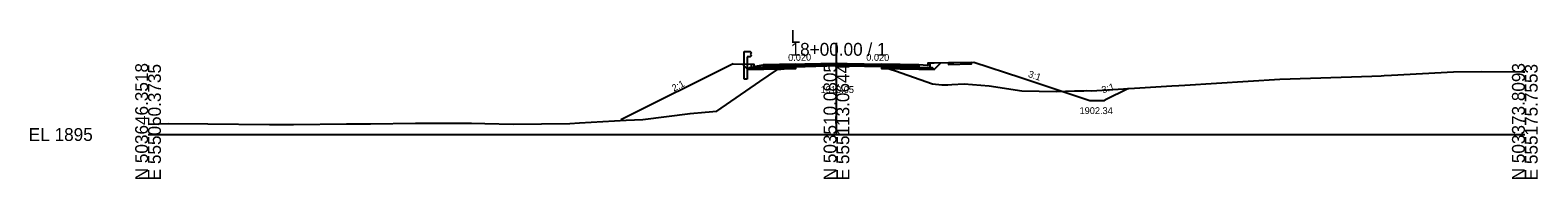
# Model space of a CAD drawing. Extents: x -26 to 4603, y -10 to 4703.
# Drawn here: x -25.7 to 302.8, y 3535.3 to 3567.8 of the extents above; entities that cross this region are included whole.
import ezdxf

# ---------------------------------------------------------------- set-up
doc = ezdxf.new("R2010")
doc.units = 0
for name, color, linetype in [('Default', 7, 'Continuous'), ('Exist Cross Section Cell', 7, 'Continuous'), ('Exist XS Ground Line', 7, 'Continuous'), ('Prop CMT Guardrail Graphics', 7, 'Continuous'), ('Prop CMT Pvmt Course 1', 7, 'Continuous'), ('Prop CMT Pvmt Course 2', 7, 'Continuous'), ('Prop CMT Pvmt Course 3', 7, 'Continuous'), ('Prop CMT Pvmt Milling', 7, 'Continuous'), ('Prop CMT Shear Line', 7, 'Continuous'), ('Prop CMT Shld Paved Course 2', 7, 'Continuous'), ('Prop CMT Shld Paved Course 3', 7, 'Continuous'), ('Prop CMT Subgrade Earthwork', 7, 'Continuous'), ('Prop Conc 4in Sidewalk', 7, 'Continuous'), ('Prop Conc Curb and Gutter', 7, 'Continuous'), ('Prop XS Ditch Slope Text', 7, 'Continuous'), ('Prop XS Finish Grade', 7, 'Continuous'), ('Prop XS Label Text', 7, 'Continuous'), ('Prop XS SS Elevation Text', 7, 'Continuous'), ('Scratch_Level_9', 7, 'Continuous')]:
    doc.layers.add(name, color=color, linetype=linetype)

msp = doc.modelspace()

# ---------------------------------------------------------------- linework, layer by layer
at = {"layer": 'Exist Cross Section Cell'}
for p, q in [((150, 3545), (150, 3565)), ((0, 3545), (150, 3545)), ((150, 3545), (300, 3545))]:
    msp.add_line(p, q, dxfattribs=at)
at = {"layer": 'Exist XS Ground Line'}
msp.add_lwpolyline([(0, 3547.27), (4.47, 3547.38), (13.05, 3547.35), (26.48, 3547.18), (28.13, 3547.18), (31.7, 3547.17), (43.21, 3547.34), (48.5, 3547.34), (58.28, 3547.49), (70.51, 3547.47), (73.36, 3547.44), (79.56, 3547.29), (91.93, 3547.41), (93.99, 3547.55), (104.17, 3548.15), (107.83, 3548.28), (118.15, 3549.59), (121.37, 3549.89), (123.97, 3550.12), (133.34, 3556.58), (137.13, 3559.17), (138.59, 3559.37), (141.18, 3559.78), (143.22, 3559.84), (150.24, 3560.06), (152.35, 3560.02), (159.79, 3559.86), (162.84, 3558.87), (170.92, 3556.08), (173, 3555.88), (174.28, 3555.83), (175.14, 3555.91), (177.8, 3556.06), (183.3, 3555.62), (190.37, 3554.57), (197.94, 3554.39), (201.84, 3554.51), (203.9, 3554.57), (204.55, 3554.6), (205.6, 3554.54), (223.12, 3555.63), (224.62, 3555.71), (225.89, 3555.78), (246.63, 3557.06), (266.66, 3557.73), (268.68, 3557.81), (269.38, 3557.85), (270.97, 3557.94), (284.46, 3558.69), (290.66, 3558.74), (299.54, 3558.67), (300, 3558.7)], dxfattribs=at)
at = {"layer": 'Prop CMT Guardrail Graphics'}
for points in [[(129.89, 3557.12), (129.89, 3563.12)], [(129.89, 3563.12), (131.23, 3563.12), (131.5, 3562.83)], [(131.5, 3562.25), (131.23, 3561.95), (130.56, 3561.95)], [(130.56, 3561.95), (130.56, 3557.12)], [(131.5, 3562.83), (131.23, 3562.54)], [(131.23, 3562.54), (131.5, 3562.25)], [(130.56, 3557.12), (129.89, 3557.12)]]:
    msp.add_lwpolyline(points, dxfattribs=at)
at = {"layer": 'Prop CMT Pvmt Course 1'}
for points in [[(141.18, 3560.38), (134, 3560.24), (134, 3559.99), (134, 3559.99), (141.18, 3560.13), (141.18, 3560.13), (141.18, 3560.13), (141.18, 3560.38), (141.18, 3560.38)], [(150, 3560.56), (150, 3560.56), (150, 3560.05), (150, 3560.05), (150, 3560.05), (143.22, 3559.84), (143.22, 3559.84), (141.18, 3559.78), (141.18, 3559.78), (141.18, 3560.38), (143.22, 3560.43), (143.22, 3560.43), (150, 3560.56)], [(159.79, 3560.36), (159.79, 3559.86), (159.79, 3559.86), (159.79, 3559.86), (152.35, 3560.02), (152.35, 3560.02), (150.24, 3560.06), (150, 3560.05), (150, 3560.05), (150, 3560.05), (150, 3560.56), (150.24, 3560.56), (150.24, 3560.56), (152.35, 3560.51), (152.35, 3560.51), (159.79, 3560.36), (159.79, 3560.36)], [(167.95, 3560.2), (159.79, 3560.36), (159.79, 3560.11), (159.79, 3560.11), (167.95, 3559.95), (167.95, 3559.95), (167.95, 3559.95), (167.95, 3560.2), (167.95, 3560.2)]]:
    msp.add_lwpolyline(points, dxfattribs=at)
at = {"layer": 'Prop CMT Pvmt Course 2'}
for points in [[(141.18, 3560.13), (134, 3559.99), (134, 3559.66), (134, 3559.66), (141.18, 3559.8), (141.18, 3559.8), (141.18, 3559.8), (141.18, 3560.13), (141.18, 3560.13)], [(167.95, 3559.95), (159.79, 3560.11), (159.79, 3559.78), (159.79, 3559.78), (167.95, 3559.62), (167.95, 3559.62), (167.95, 3559.62), (167.95, 3559.95), (167.95, 3559.95)]]:
    msp.add_lwpolyline(points, dxfattribs=at)
at = {"layer": 'Prop CMT Pvmt Course 3'}
for points in [[(141.18, 3559.8), (134, 3559.66), (134, 3559.28), (134, 3559.28), (141.18, 3559.43), (141.18, 3559.43), (141.18, 3559.43), (141.18, 3559.8), (141.18, 3559.8)], [(167.95, 3559.62), (159.79, 3559.78), (159.79, 3559.41), (159.79, 3559.41), (167.95, 3559.24), (167.95, 3559.24), (167.95, 3559.24), (167.95, 3559.62), (167.95, 3559.62)], [(167.95, 3559.62), (167.95, 3559.24), (167.95, 3559.24), (171.33, 3559.17), (170.95, 3559.55), (167.95, 3559.62), (167.95, 3559.62)]]:
    msp.add_lwpolyline(points, dxfattribs=at)
at = {"layer": 'Prop CMT Pvmt Milling'}
for points in [[(141.18, 3559.78), (143.22, 3559.84), (143.22, 3559.84), (150, 3560.05), (150, 3560.05)], [(152.35, 3560.02), (159.79, 3559.86), (159.79, 3559.86), (159.79, 3559.86), (159.79, 3559.86), (152.35, 3560.02), (152.35, 3560.02), (150.24, 3560.06), (150, 3560.05), (150, 3560.05)]]:
    msp.add_lwpolyline(points, dxfattribs=at)
at = {"layer": 'Prop CMT Shld Paved Course 2'}
for points in [[(150, 3560.31), (150, 3560.31), (150, 3559.98), (150, 3559.98), (150, 3559.98), (143.22, 3559.84), (143.22, 3559.84), (143.05, 3559.84), (141.18, 3559.78), (141.18, 3559.78), (141.18, 3559.78), (141.18, 3560.13), (143.22, 3560.18), (143.22, 3560.18), (150, 3560.31)], [(159.79, 3560.11), (159.79, 3559.78), (159.79, 3559.78), (159.79, 3559.78), (152.35, 3559.93), (152.35, 3559.93), (150.24, 3559.97), (150.24, 3559.97), (150, 3559.98), (150, 3559.98), (150, 3560.31), (150.24, 3560.31), (150.24, 3560.31), (152.35, 3560.26), (152.35, 3560.26), (159.79, 3560.11), (159.79, 3560.11)]]:
    msp.add_lwpolyline(points, dxfattribs=at)
at = {"layer": 'Prop CMT Shld Paved Course 3'}
msp.add_lwpolyline([(131, 3559.6), (134, 3559.66), (134, 3559.28), (134, 3559.28), (130.7, 3559.22), (130.7, 3559.22), (130.7, 3559.22), (131, 3559.6), (131, 3559.6)], dxfattribs=at)
at = {"layer": 'Prop CMT Subgrade Earthwork'}
for points in [[(129.54, 3560.38), (130.7, 3559.22), (130.7, 3559.22)], [(130.7, 3559.22), (141.18, 3559.43), (141.18, 3559.43)], [(171.33, 3559.18), (171.33, 3559.18), (159.79, 3559.41)], [(167.95, 3559.24), (167.95, 3559.24), (171.33, 3559.17), (172.78, 3560.62)]]:
    msp.add_lwpolyline(points, dxfattribs=at)
at = {"layer": 'Prop Conc 4in Sidewalk'}
msp.add_lwpolyline([(174.45, 3560.65), (174.45, 3560.32), (179.45, 3560.42), (179.45, 3560.75), (174.45, 3560.65)], dxfattribs=at)
at = {"layer": 'Prop Conc Curb and Gutter'}
for points in [[(132, 3559.84), (134, 3560.24), (134, 3559.66), (134, 3559.66), (131.5, 3559.61), (131.5, 3559.61), (131.5, 3559.61), (131.5, 3560.34), (132, 3560.34), (132, 3560.34), (132, 3559.84), (132, 3559.84), (132, 3559.84)], [(167.95, 3560.2), (167.95, 3560.2), (167.95, 3560.2), (167.95, 3559.62), (167.95, 3559.62), (167.95, 3559.62), (170.29, 3559.57), (170.45, 3559.56), (170.45, 3559.63), (170.45, 3560.58), (169.97, 3560.58), (169.95, 3560.58), (169.95, 3560.1), (169.95, 3560.08), (169.84, 3560.08), (167.95, 3560.2), (167.95, 3560.2)]]:
    msp.add_lwpolyline(points, dxfattribs=at)
at = {"layer": 'Prop XS Finish Grade'}
for points in [[(127.5, 3560.42), (103.05, 3548.2)], [(127.5, 3560.42), (131.5, 3560.34), (131.5, 3560.34)], [(205.25, 3552.34), (205.25, 3552.34), (190.17, 3557.35), (179.95, 3560.76), (171.3, 3560.59), (170.45, 3560.58)], [(213.66, 3555.04), (208.5, 3552.47), (208.25, 3552.34), (205.25, 3552.34), (205.25, 3552.34)]]:
    msp.add_lwpolyline(points, dxfattribs=at)
at = {"layer": 'Scratch_Level_9'}
msp.add_lwpolyline([(134, 3560.24), (134, 3559.99)], dxfattribs=at)

# ---------------------------------------------------------------- texts
at = {"layer": 'Default'}
msp.add_text('-', height=0.0001, dxfattribs=at).set_placement((0, 3545))
at = {"layer": 'Exist Cross Section Cell'}
for s, p in [('18+00.00 / 1', (140, 3562.2)), ('L', (140, 3565)), ('EL 1895', (-26, 3543.6))]:
    msp.add_text(s, height=2.8, dxfattribs=at).set_placement(p)
for s, p in [('N 503646.3518', (0, 3535)), ('E 555050.3735', (2.8, 3535)), ('N 503510.0805', (150, 3535)), ('E 555113.0644', (152.8, 3535)), ('N 503373.8093', (300, 3535)), ('E 555175.7553', (302.8, 3535))]:
    msp.add_text(s, height=2.8, rotation=90, dxfattribs=at).set_placement(p)
at = {"layer": 'Prop CMT Shear Line'}
for p in [(127.5, 3560.42), (129, 3560.39), (132, 3559.84), (134, 3560.24), (134, 3560.24), (150, 3560.56), (167.94, 3560.2), (169.95, 3560.08), (174.45, 3560.65), (179.45, 3560.75), (179.95, 3560.76), (213.66, 3555.04), (205.25, 3552.34), (104.55, 3548.17)]:
    msp.add_text('X', height=0.0025, dxfattribs=at).set_placement(p)
at = {"layer": 'Prop XS Ditch Slope Text'}
msp.add_text('1902.34', height=1.5, dxfattribs=at).set_placement((202.97, 3549.46))
at = {"layer": 'Prop XS Label Text'}
for s, rotation, p in [('0.020', 1.1458, (139.48, 3561.05)), ('0.020', 358.8542, (156.48, 3561.13)), ('3:1', 341.5961, (191.65, 3557.6)), ('2:1', 28.1018, (114.61, 3554.33)), ('3:1', 17.8153, (208.07, 3553.98))]:
    msp.add_text(s, height=1.5, rotation=rotation, dxfattribs=at).set_placement(p)
at = {"layer": 'Prop XS SS Elevation Text'}
msp.add_text('1910.05', height=1.5, dxfattribs=at).set_placement((146.57, 3554.07))

doc.saveas('drawing.dxf')
